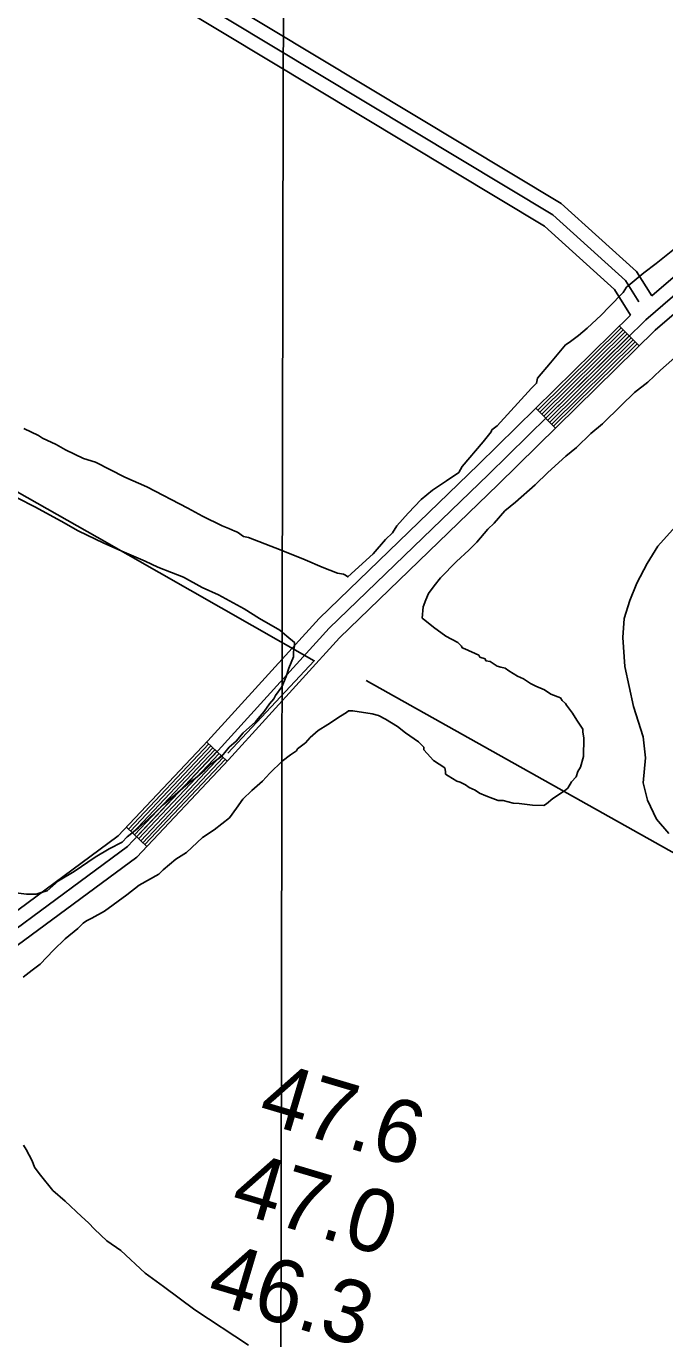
# Model space of a CAD drawing. Extents: x 3192986 to 3230865, y 867483 to 892886.
# Drawn here: x 3212615 to 3213297, y 881777 to 883165 of the extents above; entities that cross this region are included whole.
import ezdxf

# ---------------------------------------------------------------- set-up
doc = ezdxf.new("R2010")
doc.units = 0
for name, color, linetype in [('V-GRID-MAJR', 7, 'Continuous'), ('V-RIVR-RANG', 7, 'Continuous'), ('V-ROAD-CNTR', 7, 'Continuous'), ('V-SITE-VEGE', 7, 'Continuous'), ('V-TOPO-SHOR', 7, 'Continuous')]:
    doc.layers.add(name, color=color, linetype=linetype)

msp = doc.modelspace()

# ---------------------------------------------------------------- linework, layer by layer
at = {"layer": 'V-GRID-MAJR'}
msp.add_spline([(3212870.4, 872891.2), (3212881.9, 878950.4), (3212893.3, 885013.1), (3212904.8, 891075.8), (3212904.8, 891079.2)], degree=3, dxfattribs=at)
at = {"layer": 'V-ROAD-CNTR'}
for p, q in [((3213269, 882823.6), (3213247.9, 882844.9)), ((3213179.9, 882735.9), (3213158.8, 882757.2)), ((3212829.4, 882380.4), (3212807.6, 882400.9)), ((3212743.7, 882289.4), (3212721.8, 882310))]:
    msp.add_line(p, q, dxfattribs=at)
for points in [[(3214950.3, 884340.7), (3214884, 884293.4), (3214837.6, 884267.8), (3214768.4, 884239.4), (3214700.1, 884199.6), (3214637.4, 884164.4), (3214595.7, 884124.3), (3214555.7, 884067.5), (3214532, 884005.1), (3214517.8, 883962.4), (3214490.3, 883932.5), (3214450.2, 883888.4), (3214388.7, 883837.2), (3214317, 883795.5), (3214251.6, 883746.2), (3214154.3, 883648), (3214000.7, 883504), (3213897.2, 883399.3), (3213800.4, 883313.9), (3213703.5, 883239.8), (3213598.5, 883153.2), (3213509.2, 883070.4), (3213401.1, 882978.8), (3213282.5, 882876.9)], [(3212778.7, 883203.2), (3213177, 882963.6), (3213254.6, 882893.4), (3213268.8, 882870.5)], [(3212775.3, 883187.7), (3213168.1, 882951.5), (3213242.9, 882883.7), (3213259.8, 882856.6)], [(3212820.8, 883195.4), (3213186, 882975.7), (3213266.2, 882903.1), (3213282.5, 882876.9)], [(3213410.8, 882967.4), (3213276.1, 882851.6), (3213108.2, 882686.3), (3212938.3, 882522.4), (3212819.8, 882392), (3212723, 882289.4), (3212595.9, 882195.6), (3212460.7, 882075.5), (3212334.7, 881966.2), (3212166.6, 881818.1), (3212049.9, 881711.2)], [(3213420.6, 882955.9), (3213286.3, 882840.6), (3213118.7, 882675.6), (3212949.1, 882512), (3212830.8, 882381.8), (3212733, 882278.1), (3212605.3, 882183.9), (3212470.6, 882064.2), (3212344.6, 881954.9), (3212176.7, 881806.9), (3212059.8, 881699.9)], [(3213259.8, 882856.6), (3213097.7, 882697.1), (3212927.6, 882532.9), (3212808.8, 882402.2), (3212713, 882300.7), (3212586.4, 882207.2), (3212569, 882191.7)], [(3213250, 882842.8), (3213161, 882755.1)], [(3213252.1, 882840.7), (3213163.1, 882753)], [(3213254.2, 882838.5), (3213165.2, 882750.8)], [(3213256.3, 882836.4), (3213167.3, 882748.7)], [(3213258.4, 882834.3), (3213169.4, 882746.6)], [(3213260.5, 882832.1), (3213171.5, 882744.4)], [(3213262.7, 882830), (3213173.6, 882742.3)], [(3213264.8, 882827.8), (3213175.7, 882740.1)], [(3213266.9, 882825.7), (3213177.8, 882738)], [(3212809.8, 882398.9), (3212724, 882307.9)], [(3212812, 882396.8), (3212726.2, 882305.9)], [(3212814.1, 882394.8), (3212728.4, 882303.8)], [(3212816.3, 882392.7), (3212730.6, 882301.8)], [(3212818.5, 882390.7), (3212732.7, 882299.7)], [(3212820.7, 882388.6), (3212734.9, 882297.7)], [(3212822.9, 882386.5), (3212737.1, 882295.6)], [(3212825.1, 882384.5), (3212739.3, 882293.5)], [(3212827.2, 882382.4), (3212741.5, 882291.5)]]:
    msp.add_lwpolyline(points, dxfattribs=at)
at = {"layer": 'V-SITE-VEGE'}
for p, q in [((3213291.8, 882797.9), (3213310, 882813.7)), ((3213278.5, 882784.9), (3213291.8, 882797.9)), ((3213264.2, 882773.8), (3213278.5, 882784.9)), ((3213249.8, 882759.9), (3213264.2, 882773.8)), ((3213229.8, 882740.4), (3213249.8, 882759.9)), ((3213202.1, 882715.3), (3213217.4, 882730.2)), ((3213217.4, 882730.2), (3213229.8, 882740.4)), ((3213190.7, 882706.1), (3213202.1, 882715.3)), ((3213171.6, 882688.4), (3213190.7, 882706.1)), ((3213158.2, 882675.4), (3213171.6, 882688.4)), ((3213137.2, 882656.9), (3213158.2, 882675.4)), ((3213114.2, 882634.6), (3213125.7, 882647.6)), ((3213125.7, 882647.6), (3213137.2, 882656.9)), ((3213107.6, 882628.1), (3213114.2, 882634.6)), ((3213307.9, 882630.8), (3213289, 882609.9)), ((3213096, 882614.1), (3213107.6, 882628.1)), ((3213074.1, 882593.7), (3213087.4, 882605.8)), ((3213087.4, 882605.8), (3213096, 882614.1)), ((3213289, 882609.9), (3213277.5, 882591.3)), ((3213056.9, 882576.1), (3213074.1, 882593.7)), ((3213277.5, 882591.3), (3213266.6, 882570.5)), ((3213050.2, 882567.7), (3213056.9, 882576.1)), ((3213044.4, 882559.3), (3213050.2, 882567.7)), ((3213266.6, 882570.5), (3213259.2, 882552.1)), ((3213038.5, 882545.2), (3213041.5, 882552.7)), ((3213041.5, 882552.7), (3213044.4, 882559.3)), ((3213259.2, 882552.1), (3213253.1, 882532.6)), ((3213037.4, 882533), (3213038.5, 882545.2)), ((3213040.2, 882531.1), (3213037.4, 882533)), ((3213049.5, 882523.4), (3213040.2, 882531.1)), ((3213062.6, 882513.8), (3213049.5, 882523.4)), ((3213253.1, 882532.6), (3213251.5, 882512.5)), ((3213075.7, 882507), (3213062.6, 882513.8)), ((3213079.4, 882503.2), (3213075.7, 882507)), ((3213251.5, 882512.5), (3213253.9, 882481.6)), ((3213080.3, 882501.3), (3213079.4, 882503.2)), ((3213083.1, 882500.3), (3213080.3, 882501.3)), ((3213098.1, 882493.5), (3213083.1, 882500.3)), ((3213099, 882491.6), (3213098.1, 882493.5)), ((3213104.6, 882489.6), (3213099, 882491.6)), ((3213105.5, 882487.7), (3213104.6, 882489.6)), ((3213110.2, 882486.7), (3213105.5, 882487.7)), ((3213117.7, 882481.9), (3213110.2, 882486.7)), ((3213121.5, 882480.9), (3213117.7, 882481.9)), ((3213126.2, 882479.9), (3213121.5, 882480.9)), ((3213129.9, 882477), (3213126.2, 882479.9)), ((3213253.9, 882481.6), (3213263, 882438.7)), ((3213139.2, 882471.2), (3213129.9, 882477)), ((3213145.8, 882468.3), (3213139.2, 882471.2)), ((3213153.2, 882463.5), (3213145.8, 882468.3)), ((3213158.9, 882460.6), (3213153.2, 882463.5)), ((3213168.2, 882456.7), (3213158.9, 882460.6)), ((3213174.8, 882451.9), (3213168.2, 882456.7)), ((3213185.1, 882448), (3213174.8, 882451.9)), ((3213186.9, 882445.1), (3213185.1, 882448)), ((3213190.6, 882442.2), (3213186.9, 882445.1)), ((3213191.5, 882440.3), (3213190.6, 882442.2)), ((3213198, 882431.8), (3213191.5, 882440.3)), ((3213263, 882438.7), (3213273.4, 882406.4)), ((3212936.8, 882419.5), (3212950.2, 882428.7)), ((3212950.2, 882428.7), (3212956.8, 882432.4)), ((3212956.8, 882432.4), (3212958.7, 882434.3)), ((3212958.7, 882434.3), (3212963.4, 882434.2)), ((3212963.4, 882434.2), (3212984.1, 882431.1)), ((3212984.1, 882431.1), (3212990.7, 882429.1)), ((3212990.7, 882429.1), (3212998.2, 882425.2)), ((3212998.2, 882425.2), (3213011.2, 882417.5)), ((3213202.6, 882424.2), (3213198, 882431.8)), ((3213209.1, 882414.7), (3213202.6, 882424.2)), ((3212917.8, 882405.6), (3212926.4, 882413.1)), ((3212926.4, 882413.1), (3212936.8, 882419.5)), ((3213011.2, 882417.5), (3213019.6, 882410.8)), ((3213019.6, 882410.8), (3213033.6, 882401.1)), ((3213209, 882411.8), (3213209.1, 882414.7)), ((3213209.9, 882405.2), (3213209, 882411.8)), ((3212904.4, 882393.6), (3212913, 882400.1)), ((3212913, 882400.1), (3212917.8, 882405.6)), ((3213033.6, 882401.1), (3213039.2, 882395.4)), ((3213039.2, 882395.4), (3213039.2, 882392.6)), ((3213209.6, 882385.4), (3213209.9, 882405.2)), ((3213273.4, 882406.4), (3213275.7, 882384.1)), ((3212874.8, 882367.6), (3212888.2, 882380.6)), ((3212888.2, 882380.6), (3212896.8, 882387.1)), ((3212896.8, 882387.1), (3212903.5, 882391.7)), ((3212903.5, 882391.7), (3212904.4, 882393.6)), ((3213039.2, 882392.6), (3213042.9, 882388.8)), ((3213042.9, 882388.8), (3213049.4, 882381.1)), ((3213049.4, 882381.1), (3213061.5, 882373.4)), ((3213206.6, 882374.2), (3213209.6, 882385.4)), ((3213275.7, 882384.1), (3213273.2, 882357.5)), ((3212867.2, 882359.3), (3212874.8, 882367.6)), ((3213061.5, 882373.4), (3213062.4, 882369.6)), ((3213062.4, 882369.6), (3213062.3, 882366.8)), ((3213062.3, 882366.8), (3213065.1, 882364.9)), ((3213201.8, 882363.9), (3213203.7, 882369.5)), ((3213203.7, 882369.5), (3213206.6, 882374.2)), ((3212855.7, 882349.1), (3212867.2, 882359.3)), ((3213065.1, 882364.9), (3213074.5, 882359.1)), ((3213074.5, 882359.1), (3213078.2, 882358.1)), ((3213078.2, 882358.1), (3213083.9, 882355.2)), ((3213083.9, 882355.2), (3213087.6, 882352.3)), ((3213193.1, 882351.7), (3213197, 882358.3)), ((3213197, 882358.3), (3213201.8, 882363.9)), ((3213273.2, 882357.5), (3213278.1, 882338.9)), ((3212839.5, 882330.4), (3212846.2, 882339.8)), ((3212846.2, 882339.8), (3212855.7, 882349.1)), ((3213087.6, 882352.3), (3213094.1, 882349.4)), ((3213094.1, 882349.4), (3213098.8, 882346.5)), ((3213098.8, 882346.5), (3213105.4, 882343.6)), ((3213105.4, 882343.6), (3213108.2, 882342.6)), ((3213108.2, 882342.6), (3213110, 882341.6)), ((3213110, 882341.6), (3213118.5, 882338.7)), ((3213170.2, 882335.1), (3213176.9, 882340.7)), ((3213176.9, 882340.7), (3213189.3, 882349)), ((3213189.3, 882349), (3213193.1, 882351.7)), ((3213278.1, 882338.9), (3213287.4, 882318.5)), ((3212831.8, 882320.2), (3212839.5, 882330.4)), ((3213118.5, 882338.7), (3213124.1, 882338.6)), ((3213124.1, 882338.6), (3213134.5, 882335.6)), ((3213134.5, 882335.6), (3213141, 882335.5)), ((3213141, 882335.5), (3213155.2, 882333.4)), ((3213155.2, 882333.4), (3213167.4, 882333.3)), ((3213167.4, 882333.3), (3213170.2, 882335.1)), ((3212815.6, 882307.2), (3212831.8, 882320.2)), ((3213287.4, 882318.5), (3213300.7, 882303.5)), ((3212786, 882283.2), (3212803.2, 882298.9)), ((3212803.2, 882298.9), (3212815.6, 882307.2)), ((3212761.2, 882264.7), (3212774.6, 882275.8)), ((3212774.6, 882275.8), (3212786, 882283.2)), ((3212735.6, 882248.1), (3212756.5, 882260)), ((3212756.5, 882260), (3212761.2, 882264.7)), ((3212722.2, 882237.9), (3212735.6, 882248.1)), ((3212698.4, 882220.3), (3212722.2, 882237.9)), ((3212685.1, 882213), (3212698.4, 882220.3)), ((3212656.5, 882190.8), (3212669.9, 882201.9)), ((3212669.9, 882201.9), (3212675.6, 882207.5)), ((3212675.6, 882207.5), (3212679.4, 882210.2)), ((3212679.4, 882210.2), (3212685.1, 882213)), ((3212644.1, 882178.7), (3212656.5, 882190.8)), ((3212629.8, 882163.8), (3212644.1, 882178.7)), ((3212621.2, 882157.4), (3212629.8, 882163.8)), ((3212611.7, 882150), (3212621.2, 882157.4)), ((3212614.7, 881966.2), (3212611.9, 881970.9)), ((3212621.1, 881953.9), (3212614.7, 881966.2)), ((3212623.8, 881947.2), (3212621.1, 881953.9)), ((3212626.6, 881943.4), (3212623.8, 881947.2)), ((3212630.3, 881938.6), (3212626.6, 881943.4)), ((3212643.3, 881922.4), (3212630.3, 881938.6)), ((3212656.3, 881910.9), (3212643.3, 881922.4)), ((3212674, 881894.7), (3212656.3, 881910.9)), ((3212681.4, 881888), (3212674, 881894.7)), ((3212687.9, 881881.3), (3212681.4, 881888)), ((3212700.9, 881868.8), (3212687.9, 881881.3)), ((3212715.8, 881858.3), (3212700.9, 881868.8)), ((3212741.9, 881834.3), (3212715.8, 881858.3)), ((3212761.5, 881819.9), (3212741.9, 881834.3)), ((3212795, 881794.9), (3212761.5, 881819.9)), ((3212852, 881757.4), (3212795, 881794.9))]:
    msp.add_line(p, q, dxfattribs=at)
for points in [[(3213308.6, 882928.6), (3213287.2, 882911.5), (3213274.2, 882901.5), (3213255.6, 882886.2), (3213251.9, 882880.7), (3213237, 882865.3), (3213228.6, 882856.3), (3213213.7, 882842.7), (3213204.4, 882834.6), (3213194.2, 882827.4), (3213190.5, 882824.7), (3213174.6, 882805.6), (3213160.6, 882789.3), (3213159.6, 882783.8), (3213154, 882778.4), (3213117.6, 882738.5), (3213112, 882733.9), (3213111.1, 882732.1), (3213102.6, 882721.2), (3213080.2, 882694.9), (3213076.5, 882688.5), (3213063.5, 882679.5), (3213048.6, 882669.6), (3213036.5, 882659.7), (3213022.6, 882645.2), (3213010.4, 882631.6), (3213005.7, 882624.3), (3212998.3, 882617.1), (3212985.2, 882601.7), (3212958.2, 882577.2), (3212955.5, 882579.1), (3212953.6, 882580.1), (3212947.2, 882581.1), (3212930.8, 882587.7), (3212912.5, 882595.4), (3212887, 882605.8), (3212852.3, 882619.2), (3212846.8, 882620.2), (3212840.4, 882624.9), (3212837.7, 882625.8), (3212831.3, 882628.7), (3212824, 882631.5), (3212803, 882641.9), (3212787.5, 882650.4), (3212743.7, 882673.1), (3212720, 882683.5), (3212689, 882699.6), (3212676.2, 882703.5), (3212657, 882712.9), (3212647, 882718.6), (3212632.4, 882725.2), (3212627.9, 882728), (3212612.3, 882735.6)], [(3212605.8, 882661.3), (3212624, 882651.8), (3212652.3, 882636.7), (3212670.5, 882626.4), (3212697.9, 882613.1), (3212717, 882604.6), (3212741.7, 882594.1), (3212755.4, 882587.5), (3212770, 882581.8), (3212782.8, 882577), (3212802.8, 882565.7), (3212820.1, 882558.1), (3212847.5, 882543), (3212863.9, 882532.7), (3212885.7, 882520.4), (3212893, 882513.9), (3212901.2, 882507.3), (3212901.1, 882503.7), (3212900.1, 882497.2), (3212900, 882491.7), (3212895.3, 882479.9), (3212892.4, 882470.7), (3212887.6, 882459.8), (3212881.1, 882450.7), (3212879.2, 882447), (3212874.5, 882441.6), (3212868.9, 882433.4), (3212862.3, 882426.1), (3212859.5, 882422.5), (3212846.5, 882410.8), (3212839, 882401.7), (3212831.6, 882395.4), (3212826.9, 882389.9), (3212823.2, 882385.4), (3212812, 882377.3), (3212805.5, 882370.9), (3212795.3, 882361.9), (3212789.7, 882358.3), (3212782.3, 882352), (3212771.1, 882342), (3212760.9, 882333.9), (3212745.1, 882318.5), (3212734.8, 882309.5), (3212722.7, 882299.6), (3212717.2, 882294.1), (3212703.3, 882287), (3212688.4, 882278), (3212666.2, 882262.7), (3212649.5, 882252.8), (3212637.4, 882242), (3212631, 882240.2), (3212625.4, 882238.5), (3212615.3, 882238.6), (3212589.6, 882241.8)]]:
    msp.add_lwpolyline(points, dxfattribs=at)
at = {"layer": 'V-TOPO-SHOR'}
for points in [[(3211337.2, 883635.7), (3211469.6, 883488.7), (3211642.9, 883325.4), (3211775.2, 883178.4), (3211865.8, 883096.7), (3211918.4, 883057.8), (3212104.1, 882943.3), (3212268.9, 882858.3), (3212690.5, 882619.7), (3212922.3, 882487.6), (3212830, 882389.1)], [(3213307.9, 882630.8), (3213289, 882609.9), (3213277.5, 882591.3), (3213266.6, 882570.5), (3213259.2, 882552.1), (3213253.1, 882532.6), (3213251.5, 882512.5), (3213253.9, 882481.6), (3213263, 882438.7), (3213273.4, 882406.4), (3213275.7, 882384.1), (3213273.2, 882357.5), (3213278.1, 882338.9), (3213287.4, 882318.5), (3213300.7, 882303.5)], [(3212977.8, 882466.5), (3213309.8, 882280.4), (3213317.5, 882287.7)]]:
    msp.add_lwpolyline(points, dxfattribs=at)

# ---------------------------------------------------------------- texts
at = {"layer": 'V-RIVR-RANG'}
for s, p in [('47.6', (3212860.2, 881996.8)), ('47.0', (3212831, 881901.2)), ('46.3', (3212805.5, 881804.4))]:
    msp.add_text(s, height=67, rotation=343.4683, dxfattribs=at).set_placement(p)

doc.saveas('drawing.dxf')
